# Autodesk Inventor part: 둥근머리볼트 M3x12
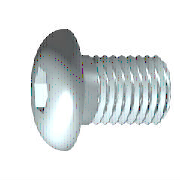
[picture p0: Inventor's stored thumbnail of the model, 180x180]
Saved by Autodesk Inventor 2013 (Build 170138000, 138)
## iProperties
IsCustomPart: 0
Created: 2012-02
Part Number: 둥근머리볼트 M3x12
Material: 강철
Description: 6각 소켓 버튼 머리 나사 - 제품 등급 A
Document SubType Name: Modeling
Standard: ISO 7380
Designer: mduedu
Standard Revision: Third edition 2004-01-15
Standards Organization: ISO
Language: ko-KR
Size Designation: M3 x 12
Categories: <MemberInstance><Categories><Category DisplayName="조임쇠" InternalName="e4da775c-781d-43d5-af7c-5136215cf5a6" Mnemonic="FSTN"><Category DisplayName="볼트" InternalN
Density: 7.85 g/cm^3
Mass: 0.90169 g
Surface Area: 1.87531 cm^2
Volume: 0.114865 cm^3
Author: mduedu
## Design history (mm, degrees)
sketch "스케치1"
  geometry: L1 (0.057, 0)-(12, 0); L2 (12, 0)-(12, 1.5); L3 (12, 1.5)-(1, 1.5); L4 (1, 1.5)-(0.693, 1.5); L5 (0.693, 1.5)-(0, 1.5); L6 (0, 1.5)-(0, 2.85); L7 (0, 2.85)-(-1.65, 2.85); L8 (-1.65, 2.85)-(-1.65, 1.155); L9 (-1.65, 1.155)-(-0.61, 1.155); L10 (-0.61, 1.155)-(0.057, 0); L11 (-4.38, 0)-(14.73, 0) reference; L12 (0, -0.57)-(0, 3.42) reference; L13 (1, 1.5)-(0, 1.5)
  constraints: 22 end point, 6 parallel, 2 collinear, 2 perpendicular, 1 horizontal, 1 point on line
  dimensions: "d1" = 11 distance from line of L3.end L2 (= GEL); "d2" = 0.30683 distance of L4.end L3.end (computed from GAL); "d3" = 1.65 distance between parallel lines of L8 L6 (= KOH); "d4" = 1.04 distance of L8.end L9.end (= INTI); "d5" = 60 deg angle of L10 L1; "d6" = 3 diameter of L3 L1 (= GD); "d7" = 3 diameter of L5 L1 (= BDM); "d8" = 2.3094 diameter of L9 L1 (= 1.1547 x SW); "d9" = 5.7 diameter of L7 L1 (= KOD); "d26" = 12 distance between parallel lines of L12 L2 (= NLG)
revolve "본체" sketch "스케치1" stored, may be unused: angle "d10" = 90 deg
sketch "스케치2"
  geometry: L1 (0, -3.99)-(0, 3.99) reference; L2 (-3.99, 0)-(3.99, 0) reference; L3 (1.155, 0)-(0.577, -1); L4 (0.577, -1)-(-0.577, -1); L5 (-0.577, -1)-(-1.155, 0); L6 (-1.155, 0)-(-0.577, 1); L7 (-0.577, 1)-(0.577, 1); L8 (0.577, 1)-(1.155, 0); 2 further points
  constraints: 12 end point, 1 coincident, 1 horizontal alignment, 1 point on line, 12 other
extrude "슬롯" join sketch "스케치2" stored distance "d11" = 10; taper "d12" = 0 deg
workplane "Work Plane1"
body "Solid1"
fillet "모깎기1" dims "d17" = 1.45 (= RR)
feature "스레드" dims "d13" = 11 (= GEL), "d14" = 0
chamfer "모따기1" distance "d15" = 0.30673 (= -0.5 x SPD + 0.5 x GD); stored, may be unused: second distance "d16" = 0.30673 (= GUL), angle "d27" = 45 deg
fillet "모깎기2" dims "d30" = 0.1 (= R)
other parameters: "GD" = 3 (= NND) [user parameter; used in 2 equation terms], "NLG" = 12 [user parameter; used in 1 equation term], "GEL" = 11 [user parameter; used in 2 equation terms], "KOD" = 5.7 [user parameter; used in 1 equation term], "KOH" = 1.65 [user parameter; used in 1 equation term], "INTI" = 1.04 [user parameter; used in 1 equation term], "GAL" = 0.30673 (= 0.61345 x PTC) [user parameter; used in 1 equation term], "GUL" = 0.30673 (= 0.61345 x PTC) [user parameter; used in 1 equation term], "BDM" = 3 (= NND) [user parameter; used in 1 equation term], "SW" = 2 [user parameter; used in 1 equation term], "RR" = 1.45 [user parameter; used in 1 equation term], "SPD" = 2.38655 (= NND - 1.2269 x PTC) [user parameter; used in 1 equation term], "d19" = 0, "d28" = 0, "d29" = 0, "R" = 0.1 [user parameter; used in 1 equation term], "TOA" = 30 deg [user parameter], "GD1" = 2.38655 (= THREADDIA - 1.2269 x PTC) [user parameter], "THREADDIA" = 3 [user parameter; used in 1 equation term], "PTC" = 0.5 [user parameter; used in 5 equation terms], "NND" = 3 [user parameter; used in 3 equation terms], "KOH1" = 0.2 [user parameter], "E0" = 2.31 [user parameter]
